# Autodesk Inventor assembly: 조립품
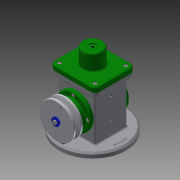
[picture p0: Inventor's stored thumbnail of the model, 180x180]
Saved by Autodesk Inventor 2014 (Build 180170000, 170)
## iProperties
Created: 2019-08
Part Number: 조립품
Document SubType Name: Assembly
Designer: NET
Author: NET
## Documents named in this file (17)
- C:\Users\NET\Desktop\490804V1018\조립품.iam
- C:\Users\NET\Desktop\490804V1018\본체.ipt
- C:\Users\NET\Desktop\490804V1018\편심축.ipt
- C:\Users\NET\Desktop\490804V1018\베어링 17 x 40 x 12.ipt
- C:\Users\NET\Desktop\490804V1018\뒤커버.ipt
- C:\Users\NET\Desktop\490804V1018\앞커버.ipt
- C:\Users\NET\Desktop\490804V1018\슬라이더.ipt
- C:\Users\NET\Desktop\490804V1018\클레비스 핀 6 x 22.ipt
- 클레비스 핀 6 x 22.ipt
- C:\Users\NET\Desktop\490804V1018\링크.ipt
- C:\Users\NET\Desktop\490804V1018\E-링.ipt
- C:\Users\NET\Desktop\490804V1018\덮개.ipt
- C:\Users\NET\Desktop\490804V1018\볼트 M4 x 8.ipt
- C:\Users\NET\Desktop\490804V1018\키 4 x 4 x 12.ipt
- C:\Users\NET\Desktop\490804V1018\V-벨트풀리.ipt
- C:\Users\NET\Desktop\490804V1018\와셔 4x16.ipt
- C:\Users\NET\Desktop\490804V1018\볼트 M4 x 10.ipt
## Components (2 placed, 2 different names)
1. E-링:1
2. V-벨트풀리:1
